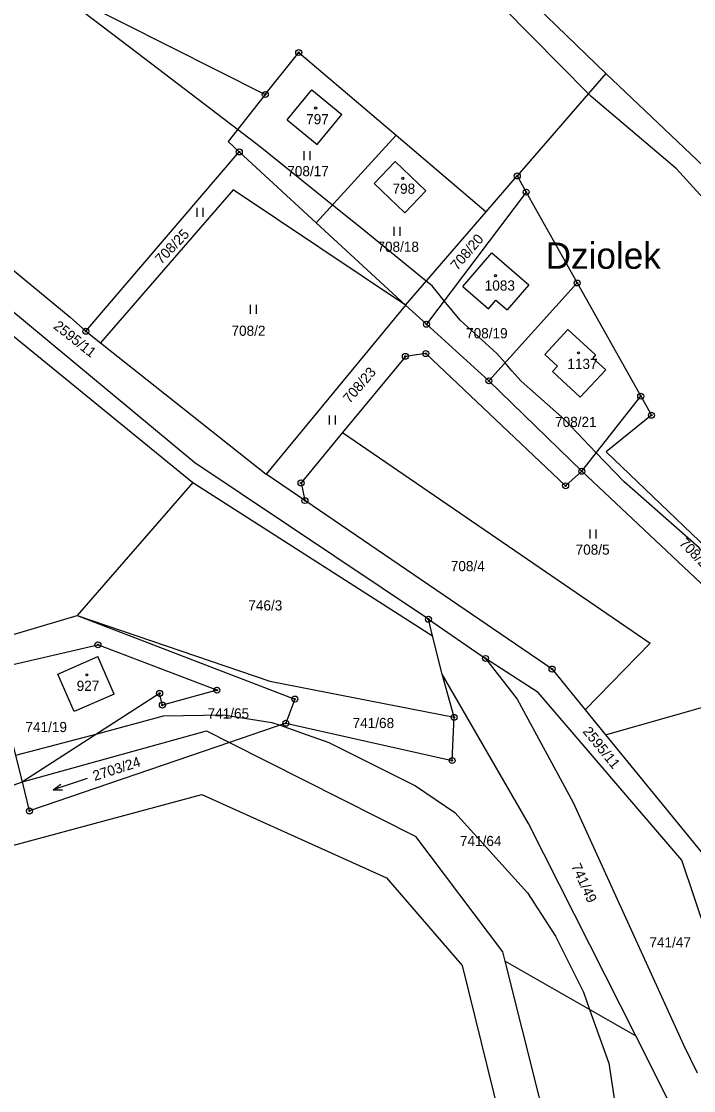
# Model space of a CAD drawing. Extents: x -439246 to -433691, y -1130252 to -1121148.
# Drawn here: x -437063.2 to -436950.7, y -1125465.5 to -1125286.5 of the extents above; entities that cross this region are included whole.
import ezdxf

# ---------------------------------------------------------------- set-up
doc = ezdxf.new("R2010")
doc.units = 0
for name, color, linetype in [('Vrstva 1', 7, 'Continuous'), ('Vrstva 15', 7, 'Continuous'), ('Vrstva 16', 7, 'Continuous'), ('Vrstva 18', 7, 'Continuous'), ('Vrstva 19', 7, 'Continuous'), ('Vrstva 24', 7, 'Continuous'), ('Vrstva 25', 7, 'Continuous'), ('Vrstva 3', 7, 'Continuous'), ('Vrstva 37', 7, 'Continuous'), ('Vrstva 52', 7, 'Continuous'), ('Vrstva 6', 7, 'Continuous')]:
    doc.layers.add(name, color=color, linetype=linetype)

msp = doc.modelspace()

# ---------------------------------------------------------------- linework, layer by layer
at = {"layer": 'Vrstva 1'}
for p, q in [((-437069.14, -1125390.53), (-437053.87, -1125385.97)), ((-437018.93, -1125404.04), (-437028.36, -1125407.26)), ((-437018.93, -1125404.04), (-436991.09, -1125410.27)), ((-436991.09, -1125410.27), (-436990.77, -1125403.04)), ((-437032.25, -1125405.3), (-437028.36, -1125407.26)), ((-437028.36, -1125407.26), (-437061.87, -1125418.71)), ((-437028.36, -1125407.26), (-436997.19, -1125423.01)), ((-437061.87, -1125418.71), (-437063.03, -1125413.84))]:
    msp.add_line(p, q, dxfattribs=at)
for points in [[(-437006.65, -1125255.28), (-436965.34, -1125295.27)], [(-437070.55, -1125274.46), (-437022.38, -1125298.77)], [(-437022.38, -1125298.77), (-437016.78, -1125291.73)], [(-437016.78, -1125291.73), (-437000.49, -1125305.57)], [(-436965.34, -1125295.27), (-436980.19, -1125312.4)], [(-437018.74, -1125302.98), (-437014.6, -1125297.97)], [(-437014.6, -1125297.97), (-437009.56, -1125302.13)], [(-437022.38, -1125298.77), (-437028.62, -1125306.61)], [(-437018.74, -1125302.98), (-437013.7, -1125307.14)], [(-437013.7, -1125307.14), (-437009.56, -1125302.13)], [(-437013.85, -1125320.24), (-437000.49, -1125305.57)], [(-437000.49, -1125305.57), (-436985.38, -1125318.4)], [(-437028.62, -1125306.61), (-437026.74, -1125308.38)], [(-437052.42, -1125338.41), (-437026.74, -1125308.38)], [(-437013.85, -1125320.24), (-437026.74, -1125308.38)], [(-437004.16, -1125313.67), (-437000.65, -1125309.97)], [(-437000.65, -1125309.97), (-436995.5, -1125314.87)], [(-436985.38, -1125318.4), (-436980.19, -1125312.4)], [(-436980.19, -1125312.4), (-436978.7, -1125315.11)], [(-437004.16, -1125313.67), (-436999.02, -1125318.56)], [(-437027.74, -1125314.71), (-437049.98, -1125340.35)], [(-436998.91, -1125334.05), (-437027.74, -1125314.71)], [(-436999.02, -1125318.56), (-436995.5, -1125314.87)], [(-436978.7, -1125315.11), (-436995.4, -1125337.23)], [(-436978.7, -1125315.11), (-436970.16, -1125330.32)], [(-437075.3, -1125319.36), (-437055.06, -1125336.04)], [(-436998.91, -1125334.05), (-436985.38, -1125318.4)], [(-436998.91, -1125334.05), (-437013.85, -1125320.24)], [(-437034.15, -1125360.42), (-437079.37, -1125322.92)], [(-436989.33, -1125330.89), (-436984.45, -1125325.25)], [(-436984.45, -1125325.25), (-436978.25, -1125330.62)], [(-437077.71, -1125328.48), (-437034.52, -1125363.71)], [(-436984.95, -1125346.7), (-436970.16, -1125330.32)], [(-436978.25, -1125330.62), (-436981.9, -1125334.84)], [(-436970.16, -1125330.32), (-436959.52, -1125349.28)], [(-436989.33, -1125330.89), (-436985, -1125334.64)], [(-436998.91, -1125334.05), (-437022.21, -1125362.34)], [(-436998.91, -1125334.05), (-436995.4, -1125337.23)], [(-436985, -1125334.64), (-436983.77, -1125333.22)], [(-436983.77, -1125333.22), (-436981.9, -1125334.84)], [(-437055.06, -1125336.04), (-437052.42, -1125338.41)], [(-436995.4, -1125337.23), (-436984.95, -1125346.7)], [(-437052.42, -1125338.41), (-437049.98, -1125340.35)], [(-436975.58, -1125342.31), (-436971.72, -1125338.11)], [(-436971.72, -1125338.11), (-436967.08, -1125342.37)], [(-437049.98, -1125340.35), (-437022.21, -1125362.34)], [(-436998.93, -1125342.6), (-437009.44, -1125355.36)], [(-436995.51, -1125342.15), (-436998.93, -1125342.6)], [(-436995.51, -1125342.15), (-436972.1, -1125364.27)], [(-436975.58, -1125342.31), (-436973.46, -1125344.26)], [(-436967.08, -1125342.37), (-436967.56, -1125342.89)], [(-436967.56, -1125342.89), (-436965.38, -1125344.88)], [(-436974.29, -1125345.16), (-436973.46, -1125344.26)], [(-436965.38, -1125344.88), (-436969.64, -1125349.43)], [(-436969.39, -1125361.84), (-436984.95, -1125346.7)], [(-436969.64, -1125349.43), (-436974.29, -1125345.16)], [(-436969.39, -1125361.84), (-436959.52, -1125349.28)], [(-436959.52, -1125349.28), (-436957.72, -1125352.47)], [(-436957.72, -1125352.47), (-436965.32, -1125358.57)], [(-437009.44, -1125355.36), (-437016.39, -1125363.8)], [(-437009.44, -1125355.36), (-436957.96, -1125390.64)], [(-436940.57, -1125382.24), (-436965.32, -1125358.57)], [(-436995.06, -1125386.63), (-437034.15, -1125360.42)], [(-437015.74, -1125366.75), (-437022.21, -1125362.34)], [(-436969.39, -1125361.84), (-436972.1, -1125364.27)], [(-436969.39, -1125361.84), (-436932.42, -1125396.62)], [(-437034.52, -1125363.71), (-437053.87, -1125385.97)], [(-437034.52, -1125363.71), (-436994.37, -1125389.4)], [(-437016.39, -1125363.8), (-437015.74, -1125366.75)], [(-436974.37, -1125394.96), (-437015.74, -1125366.75)], [(-437053.87, -1125385.97), (-437017.43, -1125399.98)], [(-437053.87, -1125385.97), (-437021.64, -1125397)], [(-436995.06, -1125386.63), (-436985.51, -1125393.18)], [(-436994.37, -1125389.4), (-436995.06, -1125386.63)], [(-436992.77, -1125395.81), (-436994.37, -1125389.4)], [(-437067.82, -1125394.94), (-437050.4, -1125390.91)], [(-437030.48, -1125398.5), (-437050.4, -1125390.91)], [(-436957.96, -1125390.64), (-436968.8, -1125401.78)], [(-437057.13, -1125395.8), (-437050.41, -1125392.86)], [(-437047.67, -1125399.14), (-437050.41, -1125392.86)], [(-436985.51, -1125393.18), (-436980.23, -1125400.01)], [(-436976.71, -1125398.9), (-436985.51, -1125393.18)], [(-437063.03, -1125413.84), (-437067.82, -1125394.94)], [(-436974.37, -1125394.96), (-436968.8, -1125401.78)], [(-437054.38, -1125402.07), (-437057.13, -1125395.8)], [(-436978.33, -1125420.82), (-436992.77, -1125395.81)], [(-436990.77, -1125403.04), (-436992.77, -1125395.81)], [(-436965.4, -1125405.95), (-436932.42, -1125396.62)], [(-437030.48, -1125398.5), (-437039.61, -1125400.99)], [(-437021.64, -1125397), (-436990.77, -1125403.04)], [(-437040.07, -1125399.03), (-437063.03, -1125413.84)], [(-437047.67, -1125399.14), (-437054.38, -1125402.07)], [(-437039.61, -1125400.99), (-437040.07, -1125399.03)], [(-437017.43, -1125399.98), (-437018.93, -1125404.04)], [(-436980.23, -1125400.01), (-436970.82, -1125417.3)], [(-436952.63, -1125426.98), (-436976.71, -1125398.9)], [(-436968.8, -1125401.78), (-436965.4, -1125405.95)], [(-437063.03, -1125413.84), (-437032.25, -1125405.3)], [(-436965.4, -1125405.95), (-436948.45, -1125426.71)], [(-437066.97, -1125415.21), (-437063.03, -1125413.84)], [(-437079.86, -1125428.55), (-437033.03, -1125415.98)], [(-437033.03, -1125415.98), (-437002.08, -1125429.89)], [(-436970.82, -1125417.3), (-436952.37, -1125457.85)], [(-436960.36, -1125456.35), (-436978.33, -1125420.82)], [(-436982.62, -1125442.3), (-436997.19, -1125423.01)], [(-436944.18, -1125452.16), (-436952.63, -1125426.98)], [(-437002.08, -1125429.89), (-436989.43, -1125444.59)], [(-436982.22, -1125443.86), (-436982.62, -1125442.3)], [(-436989.43, -1125444.59), (-436966.14, -1125538.89)], [(-436982.22, -1125443.86), (-436960.36, -1125456.35)], [(-436959.34, -1125534.94), (-436982.22, -1125443.86)], [(-436957.49, -1125462.02), (-436960.36, -1125456.35)], [(-436952.37, -1125457.85), (-436950.1, -1125462.57)], [(-436942.68, -1125491.62), (-436957.49, -1125462.02)]]:
    msp.add_lwpolyline(points, dxfattribs=at)
at = {"layer": 'Vrstva 24'}
for centre, radius in [((-437016.78, -1125291.73), 0.5), ((-437016.78, -1125291.73), 0.1), ((-437022.38, -1125298.77), 0.5), ((-437022.38, -1125298.77), 0.1), ((-437026.74, -1125308.38), 0.5), ((-437026.74, -1125308.38), 0.1), ((-436980.19, -1125312.4), 0.5), ((-436980.19, -1125312.4), 0.1), ((-436978.7, -1125315.11), 0.5), ((-436978.7, -1125315.11), 0.1), ((-436970.16, -1125330.32), 0.5), ((-436970.16, -1125330.32), 0.1), ((-436995.4, -1125337.23), 0.5), ((-436995.4, -1125337.23), 0.1), ((-437052.42, -1125338.41), 0.5), ((-437052.42, -1125338.41), 0.1), ((-436998.93, -1125342.6), 0.5), ((-436998.93, -1125342.6), 0.1), ((-436995.51, -1125342.15), 0.5), ((-436995.51, -1125342.15), 0.1), ((-436984.95, -1125346.7), 0.5), ((-436984.95, -1125346.7), 0.1), ((-436959.52, -1125349.28), 0.5), ((-436959.52, -1125349.28), 0.1), ((-436957.72, -1125352.47), 0.5), ((-436957.72, -1125352.47), 0.1), ((-436969.39, -1125361.84), 0.5), ((-436969.39, -1125361.84), 0.1), ((-437016.39, -1125363.8), 0.5), ((-437016.39, -1125363.8), 0.1), ((-436972.1, -1125364.27), 0.5), ((-436972.1, -1125364.27), 0.1), ((-437015.74, -1125366.75), 0.5), ((-437015.74, -1125366.75), 0.1), ((-436995.06, -1125386.63), 0.5), ((-436995.06, -1125386.63), 0.1), ((-437050.4, -1125390.91), 0.5), ((-437050.4, -1125390.91), 0.1), ((-436985.51, -1125393.18), 0.5), ((-436985.51, -1125393.18), 0.1), ((-436974.37, -1125394.96), 0.5), ((-436974.37, -1125394.96), 0.1), ((-437040.07, -1125399.03), 0.5), ((-437030.48, -1125398.5), 0.5), ((-437030.48, -1125398.5), 0.1), ((-437040.07, -1125399.03), 0.1), ((-437039.61, -1125400.99), 0.5), ((-437017.43, -1125399.98), 0.5), ((-437017.43, -1125399.98), 0.1), ((-437039.61, -1125400.99), 0.1), ((-437018.93, -1125404.04), 0.5), ((-437018.93, -1125404.04), 0.1), ((-436990.77, -1125403.04), 0.5), ((-436990.77, -1125403.04), 0.1), ((-436991.09, -1125410.27), 0.5), ((-436991.09, -1125410.27), 0.1), ((-437061.87, -1125418.71), 0.5), ((-437061.87, -1125418.71), 0.1)]:
    msp.add_circle(centre, radius, dxfattribs=at)
at = {"layer": 'Vrstva 25'}
for p, q in [((-437015.89, -1125309.74), (-437015.89, -1125308.24)), ((-437014.89, -1125309.74), (-437014.89, -1125308.24)), ((-437033.76, -1125319.22), (-437033.76, -1125317.72)), ((-437032.76, -1125319.22), (-437032.76, -1125317.72)), ((-437000.8, -1125322.4), (-437000.8, -1125320.9)), ((-436999.8, -1125322.4), (-436999.8, -1125320.9)), ((-437024.83, -1125335.49), (-437024.83, -1125333.99)), ((-437023.83, -1125335.49), (-437023.83, -1125333.99)), ((-437011.62, -1125354.02), (-437011.62, -1125352.52)), ((-437010.62, -1125354.02), (-437010.62, -1125352.52)), ((-436967.98, -1125373.11), (-436967.98, -1125371.61)), ((-436966.98, -1125373.11), (-436966.98, -1125371.61))]:
    msp.add_line(p, q, dxfattribs=at)
for points in [[(-437052.19, -1125413.28), (-437057.89, -1125415.16), (-437056.31, -1125415.16)], [(-437057.89, -1125415.16), (-437056.62, -1125414.21)]]:
    msp.add_lwpolyline(points, dxfattribs=at)
for centre in [(-437013.95, -1125301.03), (-436999.35, -1125312.79), (-436983.83, -1125329.1), (-436969.95, -1125342), (-437052.26, -1125395.94)]:
    msp.add_circle(centre, 0.175, dxfattribs=at)
at = {"layer": 'Vrstva 3'}
for points in [[(-437018.74, -1125302.98), (-437014.6, -1125297.97)], [(-437014.6, -1125297.97), (-437009.56, -1125302.13)], [(-437018.74, -1125302.98), (-437013.7, -1125307.14)], [(-437013.7, -1125307.14), (-437009.56, -1125302.13)], [(-437004.16, -1125313.67), (-437000.65, -1125309.97)], [(-437000.65, -1125309.97), (-436995.5, -1125314.87)], [(-437004.16, -1125313.67), (-436999.02, -1125318.56)], [(-436999.02, -1125318.56), (-436995.5, -1125314.87)], [(-436989.33, -1125330.89), (-436984.45, -1125325.25)], [(-436984.45, -1125325.25), (-436978.25, -1125330.62)], [(-436978.25, -1125330.62), (-436981.9, -1125334.84)], [(-436989.33, -1125330.89), (-436985, -1125334.64)], [(-436985, -1125334.64), (-436983.77, -1125333.22)], [(-436983.77, -1125333.22), (-436981.9, -1125334.84)], [(-436975.58, -1125342.31), (-436971.72, -1125338.11)], [(-436971.72, -1125338.11), (-436967.08, -1125342.37)], [(-436975.58, -1125342.31), (-436973.46, -1125344.26)], [(-436967.08, -1125342.37), (-436967.56, -1125342.89)], [(-436967.56, -1125342.89), (-436965.38, -1125344.88)], [(-436974.29, -1125345.16), (-436973.46, -1125344.26)], [(-436965.38, -1125344.88), (-436969.64, -1125349.43)], [(-436969.64, -1125349.43), (-436974.29, -1125345.16)], [(-437057.13, -1125395.8), (-437050.41, -1125392.86)], [(-437047.67, -1125399.14), (-437050.41, -1125392.86)], [(-437054.38, -1125402.07), (-437057.13, -1125395.8)], [(-437047.67, -1125399.14), (-437054.38, -1125402.07)]]:
    msp.add_lwpolyline(points, dxfattribs=at)
at = {"layer": 'Vrstva 37'}
for centre in [(-437013.95, -1125301.03), (-436999.35, -1125312.79), (-436983.83, -1125329.1), (-436969.95, -1125342), (-437052.26, -1125395.94)]:
    msp.add_circle(centre, 0.175, dxfattribs=at)
at = {"layer": 'Vrstva 52'}
for points in [[(-436941.6, -1125386.68), (-436938.76, -1125384.12), (-436925.23, -1125371.92), (-436889.47, -1125405.54), (-436889.23, -1125405.76), (-436886.89, -1125402.38), (-436875.88, -1125386.55), (-436876.22, -1125386.21), (-436908.61, -1125353.81), (-436922.25, -1125342.31), (-436931.41, -1125333.15), (-436940.78, -1125325.27), (-436953.56, -1125311.21), (-436967.84, -1125299.07), (-436968.26, -1125298.64), (-437001.71, -1125264.77)], [(-436941.6, -1125386.68), (-436943.55, -1125382.15), (-436949.73, -1125374.69), (-436962.3, -1125363.61), (-436966.96, -1125358.75), (-436972.31, -1125353.17), (-436979.55, -1125346.78), (-436981.09, -1125345.01), (-436982.23, -1125343.69), (-436983.6, -1125342.1), (-436989.78, -1125336.56), (-436992.43, -1125333.3), (-436994.46, -1125330.81), (-436995.43, -1125330.02), (-437006.44, -1125321.05), (-437011.14, -1125317.27), (-437023.26, -1125307.53), (-437027.05, -1125304.64), (-437043.7, -1125291.91), (-437058.77, -1125280.4)], [(-437064.15, -1125409.38), (-437050.54, -1125405.78), (-437039.41, -1125402.81), (-437029.4, -1125402.6), (-437021.31, -1125403.88), (-437019.91, -1125404.38), (-437016.31, -1125405.65), (-437011.72, -1125407.28), (-436997.23, -1125414.53), (-436990.63, -1125419), (-436978.49, -1125432.42), (-436973.8, -1125439.66), (-436969.11, -1125449.04), (-436968.08, -1125451.94), (-436964.85, -1125460.97), (-436961.02, -1125486.32)]]:
    msp.add_lwpolyline(points, dxfattribs=at)
at = {"layer": 'Vrstva 6'}
msp.add_lwpolyline([(-436965.34, -1125295.27), (-436873.55, -1125382.37)], dxfattribs=at)

# ---------------------------------------------------------------- texts
at = {"layer": 'Vrstva 15'}
msp.add_text('Dziolek', height=4.4, dxfattribs=at).set_placement((-436975.44, -1125327.94))
at = {"layer": 'Vrstva 16'}
for s, rotation, p in [('2595/11', 321.5075, (-437057.98, -1125337.8)), ('2595/11', 309.118, (-436969.33, -1125405.45)), ('741/49', 294.4716, (-436971.21, -1125427.94))]:
    msp.add_text(s, height=1.7, rotation=rotation, dxfattribs=at).set_placement(p)
at = {"layer": 'Vrstva 18'}
for s, p in [('708/17', (-437018.7, -1125312.44)), ('708/18', (-437003.61, -1125325.1)), ('708/2', (-437028.04, -1125339.16)), ('708/19', (-436988.76, -1125339.58)), ('708/21', (-436973.86, -1125354.43)), ('708/5', (-436970.42, -1125375.81)), ('708/4', (-436991.32, -1125378.57)), ('746/3', (-437025.22, -1125385.15)), ('741/65', (-437032.04, -1125403.24)), ('741/19', (-437062.54, -1125405.51)), ('741/68', (-437007.76, -1125404.84)), ('741/64', (-436989.79, -1125424.59)), ('741/47', (-436958.07, -1125441.57))]:
    msp.add_text(s, height=1.7, dxfattribs=at).set_placement(p)
for s, rotation, p in [('708/25', 46.0155, (-437039.8, -1125327.29)), ('708/20', 49.4637, (-436990.23, -1125328.32)), ('708/23', 49.4637, (-437008.24, -1125350.6)), ('708/22', 313.9695, (-436953.18, -1125374)), ('2703/24', 17.7633, (-437050.94, -1125413.71))]:
    msp.add_text(s, height=1.7, rotation=rotation, dxfattribs=at).set_placement(p)
at = {"layer": 'Vrstva 19'}
for s, p in [('797', (-437015.54, -1125303.74)), ('798', (-437001.08, -1125315.38)), ('1083', (-436985.64, -1125331.59)), ('1137', (-436971.81, -1125344.71)), ('927', (-437053.96, -1125398.61))]:
    msp.add_text(s, height=1.7, dxfattribs=at).set_placement(p)

doc.saveas('drawing.dxf')
